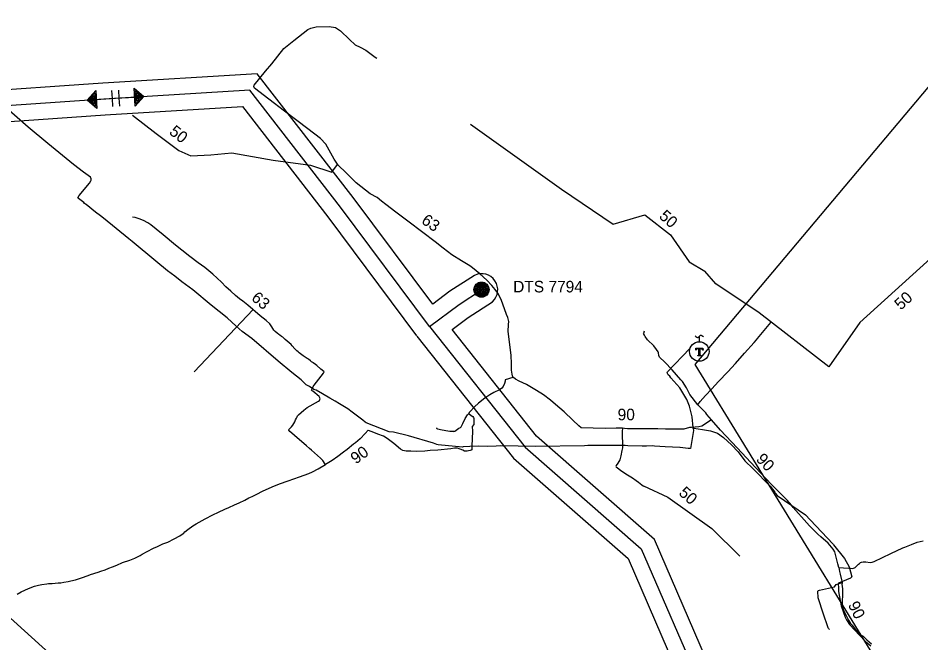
# Model space of a CAD drawing. Extents: x -444817 to -434929, y -1145681 to -1129851.
# Drawn here: x -441925 to -441301, y -1131975 to -1131543 of the extents above; entities that cross this region are included whole.
import ezdxf

# ---------------------------------------------------------------- set-up
doc = ezdxf.new("R2010")
doc.units = 0
for name, color, linetype in [('Vrstva 10', 7, 'Continuous'), ('Vrstva 11', 7, 'Continuous'), ('Vrstva 13', 7, 'Continuous'), ('Vrstva 15', 7, 'Continuous'), ('Vrstva 27', 7, 'Continuous'), ('Vrstva 30', 7, 'Continuous'), ('Vrstva 35', 7, 'Continuous'), ('Vrstva 38', 7, 'Continuous'), ('Vrstva 57', 7, 'Continuous'), ('Vrstva 58', 7, 'Continuous'), ('Vrstva 59', 7, 'Continuous')]:
    doc.layers.add(name, color=color, linetype=linetype)

msp = doc.modelspace()

# ---------------------------------------------------------------- linework, layer by layer
at = {"layer": 'Vrstva 10'}
for p, q in [((-441860.49, -1131593), (-441860.15, -1131598.59)), ((-441855.74, -1131592.71), (-441855.4, -1131598.3)), ((-441860.15, -1131598.59), (-441859.81, -1131604.18)), ((-441855.4, -1131598.3), (-441855.06, -1131603.89))]:
    msp.add_line(p, q, dxfattribs=at)
for points in [[(-441640.89, -1131756.15), (-441702.27, -1131673.76), (-441764.98, -1131592.78), (-441865.73, -1131598.93), (-441963.38, -1131605.66), (-442041.7, -1131537.14), (-442118.49, -1131453.57), (-442200.5, -1131363.12), (-442284.59, -1131268.2), (-442327.18, -1131223.28), (-442343.56, -1131201.55), (-442413.9, -1131123), (-442481.24, -1131047.9), (-442527.87, -1130994.29)], [(-441871.05, -1131599.25), (-441857.78, -1131598.44), (-441844.5, -1131597.63)], [(-441640.89, -1131756.15), (-441620.46, -1131740.89), (-441605.03, -1131730.87)], [(-441640.89, -1131756.15), (-441574.87, -1131839.72), (-441494.51, -1131910), (-441452.12, -1132008.18), (-441404.98, -1132108.37), (-441353.98, -1132209.5)]]:
    msp.add_lwpolyline(points, dxfattribs=at)
for points in [[(-441871.43, -1131592.97), (-441870.67, -1131605.54), (-441877.34, -1131599.64)], [(-441872.03, -1131594.7), (-441871.47, -1131603.9), (-441876.35, -1131599.58)], [(-441844.88, -1131591.35), (-441838.21, -1131597.25), (-441844.12, -1131603.92)], [(-441844.08, -1131592.99), (-441839.2, -1131597.31), (-441843.52, -1131602.19)], [(-441843.28, -1131594.63), (-441840.19, -1131597.37), (-441842.92, -1131600.46)], [(-441872.63, -1131596.43), (-441872.27, -1131602.26), (-441875.36, -1131599.52)], [(-441873.22, -1131598.16), (-441873.07, -1131600.61), (-441874.37, -1131599.46)], [(-441842.48, -1131596.28), (-441841.18, -1131597.43), (-441842.33, -1131598.73)]]:
    msp.add_lwpolyline(points, close=True, dxfattribs=at)
at = {"layer": 'Vrstva 11'}
for radius in [5.25, 4.55, 3.85, 3.15, 2.45, 1.75, 1.05, 0.35]:
    msp.add_circle((-441604.92, -1131730.72), radius, dxfattribs=at)
at = {"layer": 'Vrstva 15'}
for points in [[(-441638.65, -1131740.75), (-441693.51, -1131667.11), (-441759.84, -1131581.45), (-441866.44, -1131587.95), (-441959.57, -1131594.37), (-442034.01, -1131529.25), (-442110.37, -1131446.15), (-442192.31, -1131355.77), (-442276.35, -1131260.91), (-442335.34, -1131194.23), (-442405.71, -1131115.66), (-442473, -1131040.62), (-442511.53, -1130996.32)], [(-442529.12, -1131009.62), (-442489.49, -1131055.18), (-442422.09, -1131130.34), (-442351.77, -1131208.86), (-442292.83, -1131275.49), (-442208.69, -1131370.46), (-442126.61, -1131460.98), (-442049.4, -1131545.02), (-441967.18, -1131616.95), (-441865.01, -1131609.91), (-441770.12, -1131604.11), (-441711.03, -1131680.42), (-441649.71, -1131762.72)], [(-441609.7, -1131720.85), (-441626.75, -1131731.86), (-441638.65, -1131740.75)], [(-441625.25, -1131758.2), (-441614.16, -1131749.92), (-441597.4, -1131739.08)], [(-441649.52, -1131762.97), (-441582.87, -1131847.33), (-441503.62, -1131916.64), (-441462.15, -1132012.71), (-441414.87, -1132113.19), (-441362.91, -1132216.23)], [(-441347.71, -1132197.5), (-441395.09, -1132103.55), (-441442.09, -1132003.66), (-441485.39, -1131903.36), (-441566.87, -1131832.11), (-441625.25, -1131758.2)]]:
    msp.add_lwpolyline(points, dxfattribs=at)
msp.add_arc((-441604.8, -1131730.81), 11.1, 311.79584, 116.18861, dxfattribs=at)
at = {"layer": 'Vrstva 27'}
for points in [[(-441677.05, -1131667.1), (-441681.74, -1131664.53), (-441691.56, -1131656.81), (-441698.48, -1131649.99), (-441703.98, -1131644.56), (-441706.67, -1131640.55), (-441712.54, -1131630.2), (-441716.1, -1131626.14), (-441724.86, -1131619.43), (-441740.92, -1131607.3), (-441751.9, -1131599.07), (-441761.84, -1131591.38), (-441762.23, -1131590.27), (-441761.86, -1131589.31), (-441754.11, -1131579.71), (-441749.83, -1131574.51), (-441741.54, -1131564.08), (-441734.68, -1131558.56), (-441724.97, -1131550.93), (-441722.83, -1131549.96), (-441719.18, -1131549.09), (-441710.07, -1131548.75), (-441705.83, -1131549.58), (-441702.35, -1131551.9), (-441696.03, -1131557.86), (-441692.11, -1131561.49), (-441688.84, -1131563.18), (-441684.74, -1131565.09), (-441678.31, -1131569.88), (-441677.22, -1131570.76)], [(-441583.23, -1131791.47), (-441583.25, -1131791.11), (-441583.72, -1131789.23), (-441584.09, -1131786.42), (-441584.17, -1131781.66), (-441584.46, -1131776.27), (-441585.87, -1131764.86), (-441586.59, -1131759.56), (-441586.38, -1131754.73), (-441586.04, -1131752.7), (-441586.27, -1131751.87), (-441586.6, -1131750.88), (-441586.64, -1131750.01), (-441587.64, -1131747.85), (-441591.3, -1131737.49), (-441593.57, -1131733.26), (-441595.37, -1131730.66), (-441597.76, -1131727.89), (-441601.3, -1131724.13), (-441606.04, -1131719.67), (-441611.19, -1131715.7), (-441613.01, -1131714.31), (-441618.73, -1131710.72), (-441625.34, -1131706.71), (-441631.41, -1131701.93), (-441636.97, -1131697.55), (-441645.5, -1131691.28), (-441655.91, -1131683.37), (-441664.13, -1131677.07), (-441671.03, -1131671.77), (-441673.89, -1131669.63), (-441677.05, -1131667.1)], [(-441778.09, -1131731.82), (-441781.51, -1131728.74), (-441784.55, -1131725.48), (-441787.48, -1131722.84), (-441790.45, -1131720.04), (-441796.07, -1131715.42), (-441800.54, -1131712.22), (-441806.49, -1131707.75), (-441811.96, -1131703.41), (-441816.33, -1131699.98), (-441824.88, -1131692.93), (-441829.74, -1131688.85), (-441833.36, -1131685.95), (-441835.37, -1131684.48), (-441838.32, -1131682.96), (-441841.3, -1131681.74), (-441844.18, -1131680.75), (-441846.02, -1131680.63)], [(-441714.64, -1131848.83), (-441716.18, -1131847.28), (-441722.46, -1131841.71), (-441723.65, -1131840.48), (-441725.7, -1131838.67), (-441729.35, -1131835.67), (-441732.35, -1131833.15), (-441735.86, -1131829.93), (-441737.44, -1131828.68), (-441738.07, -1131827.89), (-441738.15, -1131827.59), (-441737.93, -1131827.29), (-441737.16, -1131826.46), (-441736.19, -1131825.49), (-441735.34, -1131824.45), (-441734.51, -1131823.27), (-441733.87, -1131822.18), (-441733.31, -1131820.76), (-441732.8, -1131819.51), (-441732.31, -1131818.59), (-441732.08, -1131818), (-441731.4, -1131817.26), (-441729.46, -1131815.57), (-441727.76, -1131814.05), (-441726.54, -1131813.14), (-441725.31, -1131812.24), (-441723.32, -1131811.01), (-441719.69, -1131809.01), (-441717.62, -1131807.85), (-441716.88, -1131807.37), (-441716.51, -1131806.76), (-441716.33, -1131806.21), (-441716.49, -1131805.55), (-441717.02, -1131804.65), (-441721.46, -1131800.94), (-441721.81, -1131800.65), (-441722.36, -1131800.29), (-441722.32, -1131800.12), (-441721.73, -1131798.8), (-441721.12, -1131797.68), (-441720.42, -1131796.86), (-441714.14, -1131788.4), (-441713.53, -1131787.48), (-441713.87, -1131787.25), (-441715.93, -1131785.72), (-441718.62, -1131783.26), (-441719.69, -1131782.46), (-441721.29, -1131781.26), (-441721.47, -1131781.12), (-441722.27, -1131780.52), (-441723.08, -1131779.94), (-441724.54, -1131778.89), (-441725.38, -1131778.23), (-441728.11, -1131776.38), (-441730.86, -1131774.3), (-441731.66, -1131773.7), (-441732.4, -1131773.03), (-441733.91, -1131771.66), (-441735.61, -1131769.57), (-441736.43, -1131768.57), (-441740.45, -1131765.1), (-441741.48, -1131764.29), (-441742.27, -1131763.68), (-441743.07, -1131763.08), (-441744.2, -1131762.26), (-441745, -1131761.66), (-441746.12, -1131760.72), (-441747.38, -1131759.55), (-441748.31, -1131758.62), (-441749.84, -1131756.32), (-441751.2, -1131754.38), (-441753.62, -1131752.04), (-441757.73, -1131748.72), (-441766.25, -1131741.49), (-441769.82, -1131738.66), (-441772.21, -1131737.04), (-441773.41, -1131735.93), (-441774.75, -1131734.77), (-441778.09, -1131731.82)], [(-441455.56, -1131810.46), (-441460.98, -1131803.2), (-441463.4, -1131798.49), (-441466.12, -1131794.12), (-441467.11, -1131793.01), (-441473.16, -1131786.25), (-441478.16, -1131780.92), (-441482.04, -1131777.3), (-441482.5, -1131776.13), (-441482.71, -1131774.48), (-441482.98, -1131773.71), (-441483.92, -1131772.12), (-441485.98, -1131769.66), (-441490.35, -1131765.3), (-441491.97, -1131763.04), (-441492.36, -1131762.27), (-441493.02, -1131761.12)], [(-441455.56, -1131810.46), (-441453.88, -1131808.13), (-441450.26, -1131803.99), (-441445.7, -1131799.3), (-441441.13, -1131794.21), (-441434.66, -1131787.51), (-441429.43, -1131781.69), (-441423.3, -1131774.71), (-441416.59, -1131767.31), (-441414.98, -1131765.42), (-441414.17, -1131764.45)], [(-441583.23, -1131791.47), (-441588.59, -1131793.07), (-441588.62, -1131794.1), (-441589.02, -1131795.71), (-441589.91, -1131797.6), (-441590.91, -1131798.86), (-441592.54, -1131799.95), (-441596.45, -1131801.8), (-441599.08, -1131803.44), (-441602.55, -1131805.68), (-441607.05, -1131809.21), (-441609.83, -1131811.64), (-441612.79, -1131815.02), (-441613.39, -1131815.69), (-441613.67, -1131816.25)], [(-441507.6, -1131826.56), (-441511.94, -1131826.42), (-441519.51, -1131826.73), (-441536.18, -1131826.24), (-441537.75, -1131824.8), (-441541.88, -1131821.03), (-441547.77, -1131815.29), (-441553.73, -1131810.01), (-441557.34, -1131807.06), (-441561.98, -1131803.41), (-441566.91, -1131800.36), (-441573.9, -1131796.36), (-441578.97, -1131794.03), (-441581.46, -1131792.65), (-441582.86, -1131791.35), (-441583.23, -1131791.47)], [(-441450.05, -1131815.99), (-441451.21, -1131814.75), (-441453.11, -1131812.61), (-441455.56, -1131810.46)], [(-441613.67, -1131816.25), (-441613.53, -1131816.57), (-441612.13, -1131817.7), (-441610.97, -1131818.5), (-441610.5, -1131819.17), (-441610.27, -1131819.84), (-441610.27, -1131824.03), (-441611.27, -1131825.25), (-441611.21, -1131828.49), (-441611.51, -1131838.84), (-441611.51, -1131840.36), (-441611.58, -1131841.37), (-441612.12, -1131841.74), (-441612.76, -1131841.93), (-441613.89, -1131842.23), (-441614.83, -1131842.33), (-441615.3, -1131842.43), (-441615.6, -1131842.4), (-441616.57, -1131842.37), (-441617.83, -1131841.74), (-441619.57, -1131840.99), (-441621.61, -1131840.26), (-441623.48, -1131840.35), (-441626.03, -1131840.67), (-441635.05, -1131841.63), (-441640.49, -1131842.02), (-441644.14, -1131842.32), (-441650.08, -1131842.58), (-441653.81, -1131842.37), (-441657.06, -1131842.37), (-441659.27, -1131841.91), (-441660.97, -1131840.95), (-441665.56, -1131837.14), (-441670.12, -1131833.73), (-441672.62, -1131832.06), (-441676.47, -1131830.66), (-441679.32, -1131829.54), (-441682.91, -1131828.01), (-441683.13, -1131827.84), (-441685.21, -1131830.25), (-441688.69, -1131833.76), (-441692.01, -1131836.51), (-441693.38, -1131837.62), (-441697.71, -1131841.22), (-441700.24, -1131843.05), (-441704.09, -1131845.96), (-441708.05, -1131848.84), (-441712.67, -1131851.56)], [(-441623.98, -1131828.86), (-441623.23, -1131828.49), (-441620.59, -1131826.52), (-441619.44, -1131826.02), (-441619.04, -1131825.55), (-441617.9, -1131823.35), (-441616.27, -1131819.9), (-441614.59, -1131817.34), (-441613.78, -1131816.24), (-441613.67, -1131816.25)], [(-441449.23, -1131816.97), (-441450.05, -1131815.99)], [(-441446.05, -1131820.66), (-441449.23, -1131816.97)], [(-441446.05, -1131820.66), (-441452.67, -1131825.17), (-441454.75, -1131825.5), (-441459.83, -1131825.91), (-441460.47, -1131825.94), (-441461.17, -1131826.06), (-441465.14, -1131827.24), (-441469.54, -1131827.14), (-441477.88, -1131827.12), (-441483.15, -1131827.05), (-441490.67, -1131826.91), (-441495.14, -1131826.96), (-441500.84, -1131826.99), (-441504.02, -1131827), (-441506.11, -1131826.61), (-441507.6, -1131826.56)], [(-441358.13, -1131922.69), (-441358.79, -1131920.35), (-441359.9, -1131915.58), (-441360.88, -1131912.03), (-441361.98, -1131910.11), (-441365.48, -1131906.04), (-441370.4, -1131901.57), (-441372.5, -1131899.8), (-441378.42, -1131894.03), (-441380.23, -1131891.81), (-441389.51, -1131881.32), (-441391.67, -1131878.48), (-441392.57, -1131877.6), (-441393.49, -1131876.52), (-441394.31, -1131875.72), (-441396.91, -1131873.09), (-441404.5, -1131865.38), (-441415.65, -1131853.65), (-441428.33, -1131840.06), (-441439.82, -1131827.89), (-441446.05, -1131820.66)], [(-441623.98, -1131828.86), (-441625.11, -1131828.87), (-441626.72, -1131828.86), (-441629.49, -1131828.37), (-441633.19, -1131827.62), (-441634.99, -1131827.15), (-441635.57, -1131826.88), (-441635.8, -1131826.66), (-441635.7, -1131826.17)], [(-441507.6, -1131826.56), (-441507.81, -1131828.67), (-441507.63, -1131840.06), (-441508.08, -1131842.03), (-441508.73, -1131845.5), (-441509.42, -1131848.3), (-441510.85, -1131850.74), (-441511.82, -1131852.21), (-441512.07, -1131852.74), (-441511.79, -1131853.24), (-441510.96, -1131853.85), (-441508.92, -1131855.44), (-441505.16, -1131858), (-441500.67, -1131860.78), (-441498.15, -1131862.68), (-441496.56, -1131863.83), (-441493.05, -1131866.49)], [(-441712.67, -1131851.56), (-441712.87, -1131851.32), (-441714.64, -1131848.83)], [(-441875, -1131927.67), (-441869.75, -1131926.05), (-441867.89, -1131925.4), (-441865.01, -1131924.31), (-441862.4, -1131923.32), (-441859.88, -1131922.32), (-441856.86, -1131921.13), (-441852.82, -1131919.46), (-441847.87, -1131917.74), (-441844.4, -1131916.28), (-441840.81, -1131914.45), (-441839.41, -1131913.62), (-441835.84, -1131911.74), (-441831.41, -1131909.53), (-441828.77, -1131908.18), (-441825.02, -1131906.55), (-441821.53, -1131905.26), (-441817.17, -1131903.05), (-441813.24, -1131900.85), (-441810.91, -1131899.22), (-441810.59, -1131898.98), (-441809.88, -1131898.1), (-441807.88, -1131896.6), (-441804.44, -1131894.11), (-441802.14, -1131892.73), (-441795.87, -1131889.1), (-441790.46, -1131886.42), (-441786.58, -1131884.62), (-441782.27, -1131882.58), (-441779.42, -1131881.29), (-441775.47, -1131879.49), (-441772.41, -1131877.99), (-441768.49, -1131876.15), (-441765.58, -1131874.69), (-441763.43, -1131873.71), (-441760.19, -1131872.06), (-441756.2, -1131870.05), (-441749.53, -1131867.03), (-441744.56, -1131864.94), (-441738.43, -1131862.86), (-441730.56, -1131860.18), (-441724.24, -1131857.76), (-441721.62, -1131856.69), (-441717.82, -1131854.67), (-441712.67, -1131851.56)], [(-441358.13, -1131922.69), (-441354.92, -1131923.14), (-441351.08, -1131923.27), (-441348.51, -1131923.55), (-441346.86, -1131922.76), (-441344.55, -1131920.44), (-441343.84, -1131919.97), (-441343.07, -1131919.39), (-441342.48, -1131919.12), (-441341.16, -1131918.91), (-441339.46, -1131918.87), (-441336.4, -1131919.34), (-441334.98, -1131919.16), (-441333.61, -1131918.55), (-441322.23, -1131913.07), (-441313.82, -1131909.29), (-441312.44, -1131908.72), (-441307.93, -1131906.86), (-441304, -1131905.38), (-441299.7, -1131904.32)], [(-441358.13, -1131922.69), (-441357.53, -1131925.58), (-441357.16, -1131927.39), (-441356.14, -1131931.35), (-441355.68, -1131933.13)], [(-441925.72, -1131941.34), (-441922.95, -1131939.52), (-441917.81, -1131937.3), (-441913.73, -1131935.73), (-441910.87, -1131934.94), (-441908.58, -1131934.49), (-441905.3, -1131934.06), (-441904.06, -1131933.9), (-441901.53, -1131933.83), (-441897.38, -1131933.48), (-441895.62, -1131933.32), (-441893.43, -1131933.03), (-441890.54, -1131932.51), (-441888.6, -1131932.1), (-441885.31, -1131931.25), (-441879.9, -1131929.41), (-441875.39, -1131927.79), (-441875, -1131927.67)], [(-441372.17, -1131938.81), (-441371.41, -1131938.44), (-441360.98, -1131936.18), (-441359.86, -1131934.57), (-441355.68, -1131933.13)], [(-441355.68, -1131933.13), (-441355.76, -1131933.81), (-441355.92, -1131934.32), (-441355.64, -1131937.61), (-441355.52, -1131942.17), (-441355.76, -1131945.82), (-441355.79, -1131947.95), (-441354.98, -1131951.96), (-441354.1, -1131953.73), (-441351.35, -1131959.24), (-441349.91, -1131961.59), (-441348.88, -1131962.77), (-441346.74, -1131965.52), (-441344.23, -1131968.84), (-441341.18, -1131970.39), (-441338.66, -1131972.82), (-441335.56, -1131975.54)], [(-441364.45, -1131965.57), (-441365.15, -1131964.99), (-441365.45, -1131964.56), (-441365.64, -1131963.79), (-441368.63, -1131954.97), (-441372.28, -1131943.86), (-441372.47, -1131939.25), (-441372.17, -1131938.81)]]:
    msp.add_lwpolyline(points, dxfattribs=at)
at = {"layer": 'Vrstva 35'}
for p, q in [((-441762.67, -1131744.46), (-441803.48, -1131787.61)), ((-441414.17, -1131764.45), (-441405.01, -1131753.35))]:
    msp.add_line(p, q, dxfattribs=at)
for points in [[(-441846.09, -1131610.06), (-441829.73, -1131622.78), (-441814.04, -1131634.63), (-441805.75, -1131638.18), (-441791.83, -1131637.59), (-441777.32, -1131636.11), (-441748.9, -1131641.14), (-441723.14, -1131644.69), (-441708.34, -1131649.43), (-441704.49, -1131644.1)], [(-441612.43, -1131616.42), (-441549.64, -1131661.27), (-441513.91, -1131685.5), (-441492.05, -1131679.09), (-441474.26, -1131692.79), (-441461.44, -1131711.45), (-441450.65, -1131717.86)], [(-441172.15, -1131804.57), (-441243.8, -1131736.77), (-441282.88, -1131700.35), (-441289.98, -1131704.79), (-441343.57, -1131753.35), (-441364.89, -1131784.14), (-441413.15, -1131746.84), (-441443.07, -1131726.61), (-441450.65, -1131717.86)], [(-441492.59, -1131759.5), (-441493.02, -1131761.12)], [(-441493.03, -1131866.42), (-441476.22, -1131874.15), (-441445.72, -1131895.91), (-441426.48, -1131915.01)]]:
    msp.add_lwpolyline(points, dxfattribs=at)
at = {"layer": 'Vrstva 57'}
for p, q in [((-441454.46, -1131762.99), (-441454.46, -1131766.74)), ((-441456.54, -1131772.31), (-441456.88, -1131771.97)), ((-441456.2, -1131771.94), (-441456.81, -1131771.33)), ((-441455.85, -1131771.58), (-441456.18, -1131771.25)), ((-441455.14, -1131771.58), (-441455.47, -1131771.25)), ((-441454.01, -1131772.01), (-441454.76, -1131771.25)), ((-441454.01, -1131772.72), (-441454.73, -1131771.99)), ((-441454.01, -1131773.43), (-441454.73, -1131772.7)), ((-441454.01, -1131774.13), (-441454.73, -1131773.41)), ((-441454.01, -1131774.84), (-441454.73, -1131774.11)), ((-441454.01, -1131775.55), (-441454.73, -1131774.82)), ((-441453.77, -1131776.49), (-441454.73, -1131775.53)), ((-441453.73, -1131771.58), (-441454.06, -1131771.25)), ((-441453.02, -1131771.58), (-441453.35, -1131771.25)), ((-441451.85, -1131772.04), (-441452.64, -1131771.25)), ((-441451.94, -1131771.25), (-441452.05, -1131771.14)), ((-441455.18, -1131776.49), (-441455.42, -1131776.26)), ((-441454.48, -1131776.49), (-441455.03, -1131775.94))]:
    msp.add_line(p, q, dxfattribs=at)
msp.add_lwpolyline([(-441457.37, -1131762.55), (-441456.85, -1131763.18), (-441456.2, -1131763.68), (-441455.81, -1131763.8), (-441455.4, -1131763.73), (-441454.88, -1131763.42), (-441454.46, -1131762.99), (-441454.04, -1131762.56), (-441453.52, -1131762.25), (-441453.12, -1131762.18), (-441452.72, -1131762.3), (-441452.07, -1131762.8), (-441451.56, -1131763.44)], dxfattribs=at)
msp.add_lwpolyline([(-441451.95, -1131771.14), (-441451.8, -1131772.53), (-441451.99, -1131772.53), (-441452.87, -1131771.58), (-441454.01, -1131771.58), (-441454.01, -1131775.7), (-441453.26, -1131776.31), (-441453.26, -1131776.49), (-441455.48, -1131776.49), (-441455.48, -1131776.31), (-441454.73, -1131775.7), (-441454.73, -1131771.58), (-441455.87, -1131771.58), (-441456.75, -1131772.53), (-441456.93, -1131772.53), (-441456.79, -1131771.14), (-441456.61, -1131771.14), (-441456.28, -1131771.25), (-441452.46, -1131771.25), (-441452.13, -1131771.14)], close=True, dxfattribs=at)
msp.add_circle((-441454.46, -1131773.49), 6.75, dxfattribs=at)
at = {"layer": 'Vrstva 58'}
for points in [[(-441878.57, -1131671.56), (-441879.15, -1131671.08), (-441879.67, -1131670.49), (-441883.29, -1131667.73), (-441883.76, -1131667.27), (-441882.79, -1131665.56), (-441875.82, -1131657.15), (-441874.74, -1131655.41), (-441874.6, -1131654.98), (-441874.47, -1131654.2), (-441875.13, -1131652.96), (-441879.88, -1131649.48), (-441886.68, -1131644.17), (-441896.93, -1131635.89), (-441904.52, -1131629.61), (-441918.17, -1131618.47), (-441941.18, -1131598.43)], [(-441458.63, -1131826.71), (-441458.45, -1131828.03), (-441460.51, -1131840.6), (-441462.12, -1131840.58), (-441464.01, -1131840.2), (-441467.67, -1131839.86), (-441467.92, -1131839.9), (-441478.07, -1131839.27), (-441485.5, -1131838.9), (-441486.57, -1131838.6), (-441491, -1131838.87), (-441493.98, -1131838.95), (-441503.91, -1131838.71), (-441505.64, -1131838.46), (-441505.98, -1131838.47), (-441530.08, -1131838.49), (-441531.52, -1131838.53), (-441533.72, -1131838.76), (-441567.68, -1131839.09), (-441591.58, -1131838.73), (-441594.77, -1131838.96), (-441600.69, -1131839.14), (-441606.95, -1131838.94), (-441612.91, -1131839.12), (-441617.7, -1131839.49), (-441617.97, -1131839.5), (-441634.83, -1131838.06), (-441635.82, -1131837.78), (-441638.02, -1131836.83), (-441655.24, -1131831.82), (-441665.71, -1131829.16), (-441668.69, -1131828.93), (-441684.67, -1131822.68), (-441685.22, -1131822.25), (-441686.81, -1131821.03), (-441694.23, -1131815.47), (-441697.16, -1131813.15), (-441702.91, -1131809.66), (-441705.91, -1131807.71), (-441709.65, -1131805.7), (-441714.68, -1131802.65), (-441719.2, -1131800.22), (-441720.67, -1131799.7), (-441723.83, -1131797.78), (-441726.03, -1131796.59), (-441729.61, -1131793.13), (-441736.02, -1131787.93), (-441745.38, -1131780.14), (-441763.65, -1131764.4), (-441770.18, -1131759.64), (-441774.35, -1131755.93), (-441780.7, -1131750.14), (-441791.7, -1131741.33), (-441804.3, -1131730.85), (-441811.89, -1131725.23), (-441816.66, -1131721.36), (-441821.8, -1131717.65), (-441829.96, -1131711.09), (-441846.23, -1131697.37), (-441848.57, -1131695.52), (-441866.12, -1131681.21), (-441868.12, -1131679.75), (-441871.49, -1131677.15), (-441877.91, -1131671.96), (-441878.57, -1131671.56)], [(-441458.63, -1131826.71), (-441458.75, -1131826.12), (-441459.43, -1131818.67), (-441461.19, -1131811.2), (-441463.08, -1131806.71), (-441467.94, -1131798.65), (-441474.04, -1131791.71), (-441474.91, -1131790.55), (-441475.86, -1131789.68), (-441476.57, -1131788.32), (-441476.35, -1131787.48), (-441460.9, -1131771.48)], [(-441458.63, -1131826.71), (-441458.13, -1131826.59), (-441452.15, -1131827.4), (-441446.66, -1131828.34), (-441442, -1131829.88), (-441437.74, -1131832.86), (-441432.15, -1131838.08), (-441427.71, -1131842.93), (-441422.92, -1131849), (-441417.2, -1131854.58), (-441405.44, -1131866.62), (-441402.28, -1131870.8), (-441401.85, -1131871.61), (-441400.63, -1131872.95), (-441381.21, -1131886.47), (-441377.89, -1131889.75), (-441362.06, -1131906.6), (-441361.76, -1131907.03), (-441354.05, -1131916.59), (-441350.84, -1131922.38), (-441349.16, -1131929.28), (-441350.04, -1131930.19), (-441358.27, -1131933.58), (-441358.62, -1131934.44), (-441358.41, -1131936.74), (-441358.24, -1131939.5), (-441356.49, -1131949.24), (-441353.69, -1131957.19), (-441352.86, -1131959.02), (-441350.64, -1131962.3), (-441346.93, -1131966.02), (-441343.79, -1131969.58), (-441339.7, -1131973.9), (-441335.89, -1131976.97)]]:
    msp.add_lwpolyline(points, dxfattribs=at)
at = {"layer": 'Vrstva 59'}
for points in [[(-443357.81, -1130664.34), (-442622.23, -1131330.87), (-441886.65, -1131997.4), (-441341.88, -1132491.05)], [(-440854.12, -1131064.05), (-441457.58, -1131782.51), (-441240.62, -1132136.45)]]:
    msp.add_lwpolyline(points, dxfattribs=at)

# ---------------------------------------------------------------- texts
at = {"layer": 'Vrstva 13'}
msp.add_text('DTS 7794', height=8, dxfattribs=at).set_placement((-441583.05, -1131732.63))
at = {"layer": 'Vrstva 30'}
for s, rotation, p in [('63', 325.53922, (-441647.03, -1131684.4)), ('63', 319.68235, (-441764.46, -1131737.39)), ('90', 0.30155, (-441510.85, -1131821.07)), ('90', 35.87897, (-441691.74, -1131851.62)), ('90', 313.54788, (-441415.77, -1131848.39)), ('90', 296.46099, (-441351.97, -1131948.57))]:
    msp.add_text(s, height=8, rotation=rotation, dxfattribs=at).set_placement(p)
at = {"layer": 'Vrstva 38'}
for rotation, p in [(322.01317, (-441821.23, -1131622.69)), (318.19916, (-441482.79, -1131680.75)), (42.17901, (-441315.25, -1131745.23)), (318.2295, (-441469.19, -1131872.05))]:
    msp.add_text('50', height=8, rotation=rotation, dxfattribs=at).set_placement(p)

doc.saveas('drawing.dxf')
